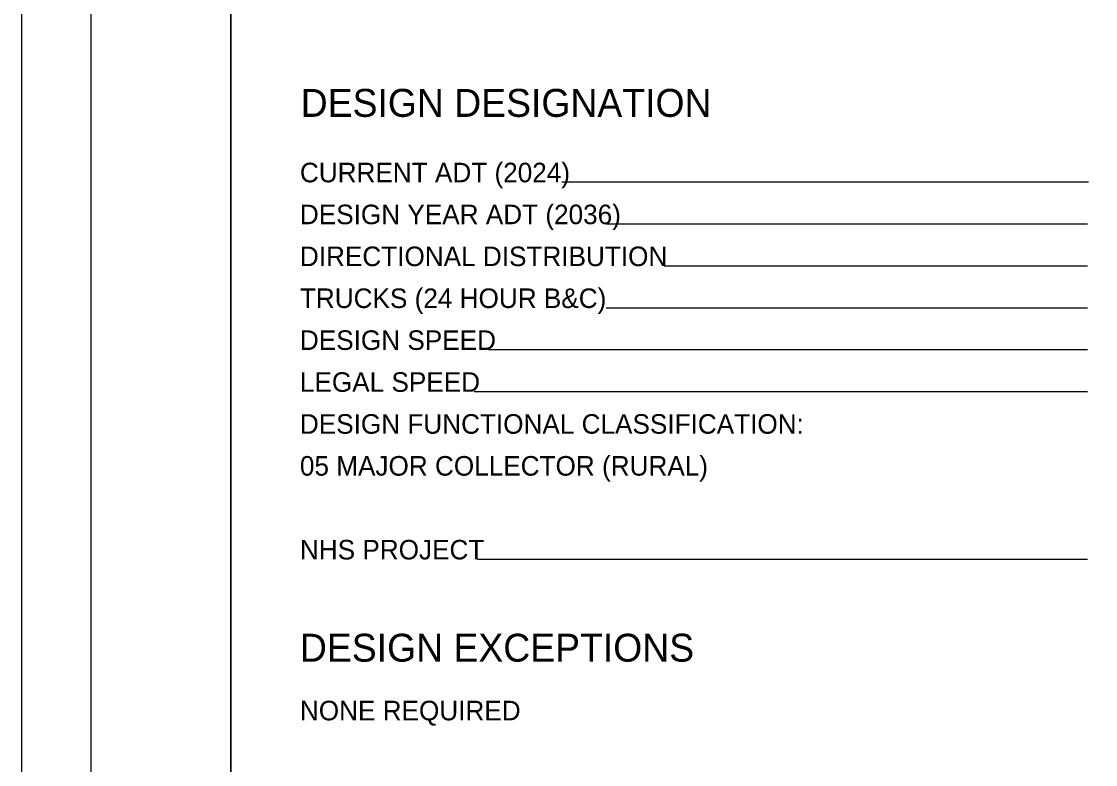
# Model space of a CAD drawing. Extents: x 0 to 34, y 0 to 22.
# Drawn here: x 0 to 7.69, y 5.64 to 10.96 of the extents above; entities that cross this region are included whole.
import ezdxf

# ---------------------------------------------------------------- set-up
doc = ezdxf.new("R2010")
doc.units = 0
for name, color, linetype in [('SC_Scratch9', 7, 'Continuous'), ('SH_Border', 7, 'Continuous'), ('SH_Cut_Line', 7, 'Continuous'), ('SH_Data', 7, 'Continuous')]:
    doc.layers.add(name, color=color, linetype=linetype)

msp = doc.modelspace()

# ---------------------------------------------------------------- linework, layer by layer
at = {"layer": 'SH_Border'}
msp.add_lwpolyline([(0, 0), (34, 0), (34, 22), (0, 22)], close=True, dxfattribs=at)
at = {"layer": 'SH_Cut_Line'}
for p, q in [((7.6424, 9.8062), (3.871, 9.8062)), ((7.6368, 9.5062), (4.1885, 9.5062)), ((7.6368, 9.2062), (4.6037, 9.2062)), ((7.6368, 8.9062), (4.1885, 8.9062)), ((7.6368, 8.6062), (3.346, 8.6062)), ((7.6368, 8.3062), (3.2422, 8.3062)), ((7.6368, 7.1062), (3.2669, 7.1062))]:
    msp.add_line(p, q, dxfattribs=at)
at = {"layer": 'SH_Data'}
for points in [[(0.5, 21.5), (1.5, 21.5), (1.5, 0.5), (0.5, 0.5)], [(1.5, 21.5), (33.5, 21.5), (33.5, 0.5), (1.5, 0.5)]]:
    msp.add_lwpolyline(points, close=True, dxfattribs=at)

# ---------------------------------------------------------------- texts
at = {"layer": 'SC_Scratch9'}
for s, height, p in [('CURRENT ADT (2024)', 0.14, (1.9944, 9.8062)), ('DESIGN YEAR ADT (2036)', 0.14, (1.9944, 9.5062)), ('DIRECTIONAL DISTRIBUTION', 0.14, (1.9944, 9.2062)), ('TRUCKS (24 HOUR B&C)', 0.14, (1.9944, 8.9062)), ('DESIGN SPEED', 0.14, (1.9944, 8.6062)), ('LEGAL SPEED', 0.14, (1.9944, 8.3062)), ('DESIGN FUNCTIONAL CLASSIFICATION:', 0.14, (1.9944, 8.0062)), ('05 MAJOR COLLECTOR (RURAL)', 0.14, (1.9944, 7.7062)), ('NHS PROJECT', 0.14, (1.9944, 7.1062)), ('DESIGN EXCEPTIONS', 0.2, (1.9944, 6.3744)), ('NONE REQUIRED', 0.14, (1.9944, 5.9544))]:
    msp.add_text(s, height=height, dxfattribs=at).set_placement(p)
at = {"layer": 'SH_Cut_Line'}
msp.add_text('DESIGN DESIGNATION', height=0.2, dxfattribs=at).set_placement((2, 10.2747))

doc.saveas('drawing.dxf')
